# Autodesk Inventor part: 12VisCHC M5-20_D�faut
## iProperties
Created: 2011-01
Part Number: 12VisCHC M5-20_D�faut
Document SubType Name: Modeling
Designer: eric
Density: 1 g/cm^3
Mass: 0.638556 g
Surface Area: 5.8504 cm^2
Volume: 0.638556 cm^3
Author: eric
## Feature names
1. Base1
